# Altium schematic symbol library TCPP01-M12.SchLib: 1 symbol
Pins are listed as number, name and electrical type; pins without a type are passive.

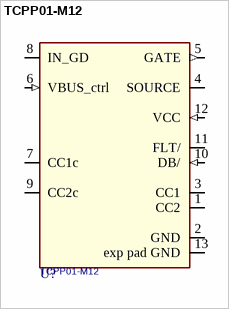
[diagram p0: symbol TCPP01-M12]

## TCPP01-M12
designator U?
footprint ST_QFN50P300x300x75-12L
pins: 1 CC2 (io), 2 GND (power), 3 CC1 (io), 4 SOURCE (power), 5 GATE (out), 6 VBUS_ctrl (in), 7 CC1c (io), 8 IN_GD (power), 9 CC2c (io), 10 DB/ (in), 11 FLT/ (oc), 12 VCC (in), 13 exp pad GND (power)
